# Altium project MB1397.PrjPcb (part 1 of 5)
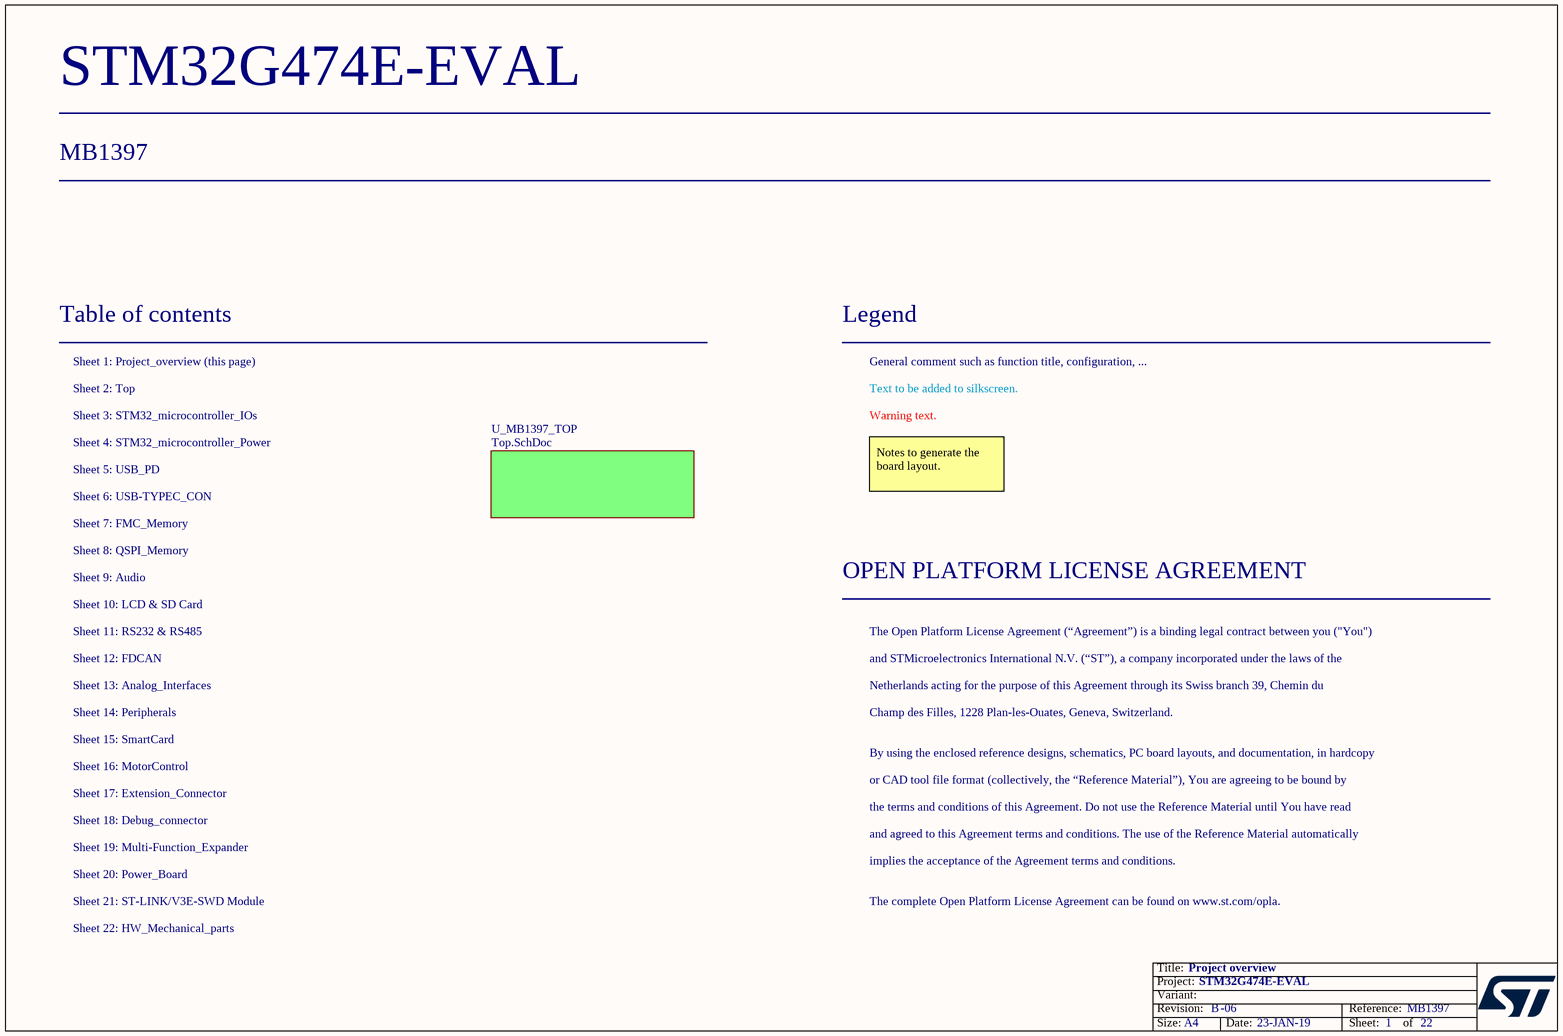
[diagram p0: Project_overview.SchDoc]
Board_Reference: MB1397; Board_PCB_Revision: B; Board_Name: STM32G474E-EVAL; Board_Document_Date: 23-JAN-19; Board_Assembly_Revision: 06
22 sheets, 834 parts. Net scope: flat (ports and power ports of the same name join across sheets).
Board file: MB1397.PcbDoc
Sheets:
  Project_overview.SchDoc
    U_MB1397_TOP = Top.SchDoc
      U_STM32_microcontroller_IOs = STM32_microcontroller_IOs.SchDoc
      U_FMC Memory = FMC_Memory.SchDoc
      U_Audio = Audio.SchDoc
      U_QSPI Memory = QSPI_Memory.SchDoc
      U_FDCAN = FDCAN.SchDoc
      U_LCD&SDcard = LCD&SDcard.SchDoc
      U_MotorControl = MotorControl.SchDoc
      U_SmartCard = SmartCard.SchDoc
      U_STM32_microcontroller_power = STM32_microcontroller_power.SchDoc
      U_Power_Board = Power_Board.SchDoc
      U_HW_Mechanical_Parts = HW_Mechanical_Parts.SchDoc
      U_Analog Interfaces = Analog_Interfaces.SchDoc
      U_Multi-Function Expander = Multi-Function_Expander.SchDoc
      U_Peripherals = Peripherals.SchDoc
      U_STLink_V3E_SWD = STLink_V3E_SWD.SchDoc
      U_ExtensionConnector = ExtensionConnector.SchDoc
      U_USB_PD = USB_PD.SchDoc
      U_Debug connector = Debug_connector.SchDoc
      U_RS232&RS485 = RS232&RS485.SchDoc
      U_USB-TYPEC_CON = USB-TYPEC_CON.SchDoc

## Sheet Project_overview.SchDoc: Project overview
size A4; IsUserConfigurable: Not used; Date: Not used; ApprovedBy: Not used; CheckedBy: Not used; Author: Not used; CompanyName: STMicroelectronics; DrawnBy: Not used; Engineer: Not used; Organization: Not used; Address1: Not used; Address2: Not used; Address3: Not used; Address4: Not used; DocumentNumber: Not used; Revision: Not used; SheetNumber: 1; SheetTotal: 22

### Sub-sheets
U_MB1397_TOP = Top.SchDoc: no entries

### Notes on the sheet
- Table of contents
- Sheet 1: Project_overview (this page)
- Legend
- General comment such as function title, configuration, ...
- Sheet 2: Top
- Sheet 4: STM32_microcontroller_Power
- Sheet 3: STM32_microcontroller_IOs
- Text to be added to silkscreen.
- Warning text.
- Sheet 6: USB-TYPEC_CON
- Sheet 5: USB_PD
- Notes to generate the board layout.
- Sheet 8: QSPI_Memory
- Sheet 7: FMC_Memory
- Sheet 9: Audio
- OPEN PLATFORM LICENSE AGREEMENT
- Sheet 10: LCD & SD Card
- Sheet 11: RS232 & RS485
- The Open Platform License Agreement (“Agreement”) is a binding legal contract between you ("You")
- Sheet 14: Peripherals
- Sheet 12: FDCAN
- Sheet 13: Analog_Interfaces
- and STMicroelectronics International N.V. (“ST”), a company incorporated under the laws of the
- Netherlands acting for the purpose of this Agreement through its Swiss branch 39, Chemin du
- Champ des Filles, 1228 Plan-les-Ouates, Geneva, Switzerland.
- Sheet 16: MotorControl
- Sheet 15: SmartCard
- By using the enclosed reference designs, schematics, PC board layouts, and documentation, in hardcopy
- or CAD tool file format (collectively, the “Reference Material”), You are agreeing to be bound by
- Sheet 18: Debug_connector
- Sheet 17: Extension_Connector
- Sheet 19: Multi-Function_Expander
- the terms and conditions of this Agreement. Do not use the Reference Material until You have read
- and agreed to this Agreement terms and conditions. The use of the Reference Material automatically
- Sheet 20: Power_Board
- Sheet 21: ST-LINK/V3E-SWD Module
- implies the acceptance of the Agreement terms and conditions.
- The complete Open Platform License Agreement can be found on www.st.com/opla.
- Sheet 22: HW_Mechanical_parts

## Sheet Top.SchDoc: MB1397 TOP
size A3; Date: Not used; ApprovedBy: Not used; CheckedBy: Not used; Author: Not used; CompanyName: STMicroelectronics; DrawnBy: Not used; Engineer: Not used; Organization: Not used; Address1: Not used; Address2: Not used; Address3: Not used; Address4: Not used; DocumentNumber: Not used; Revision: Not used; SheetNumber: 2; SheetTotal: 22
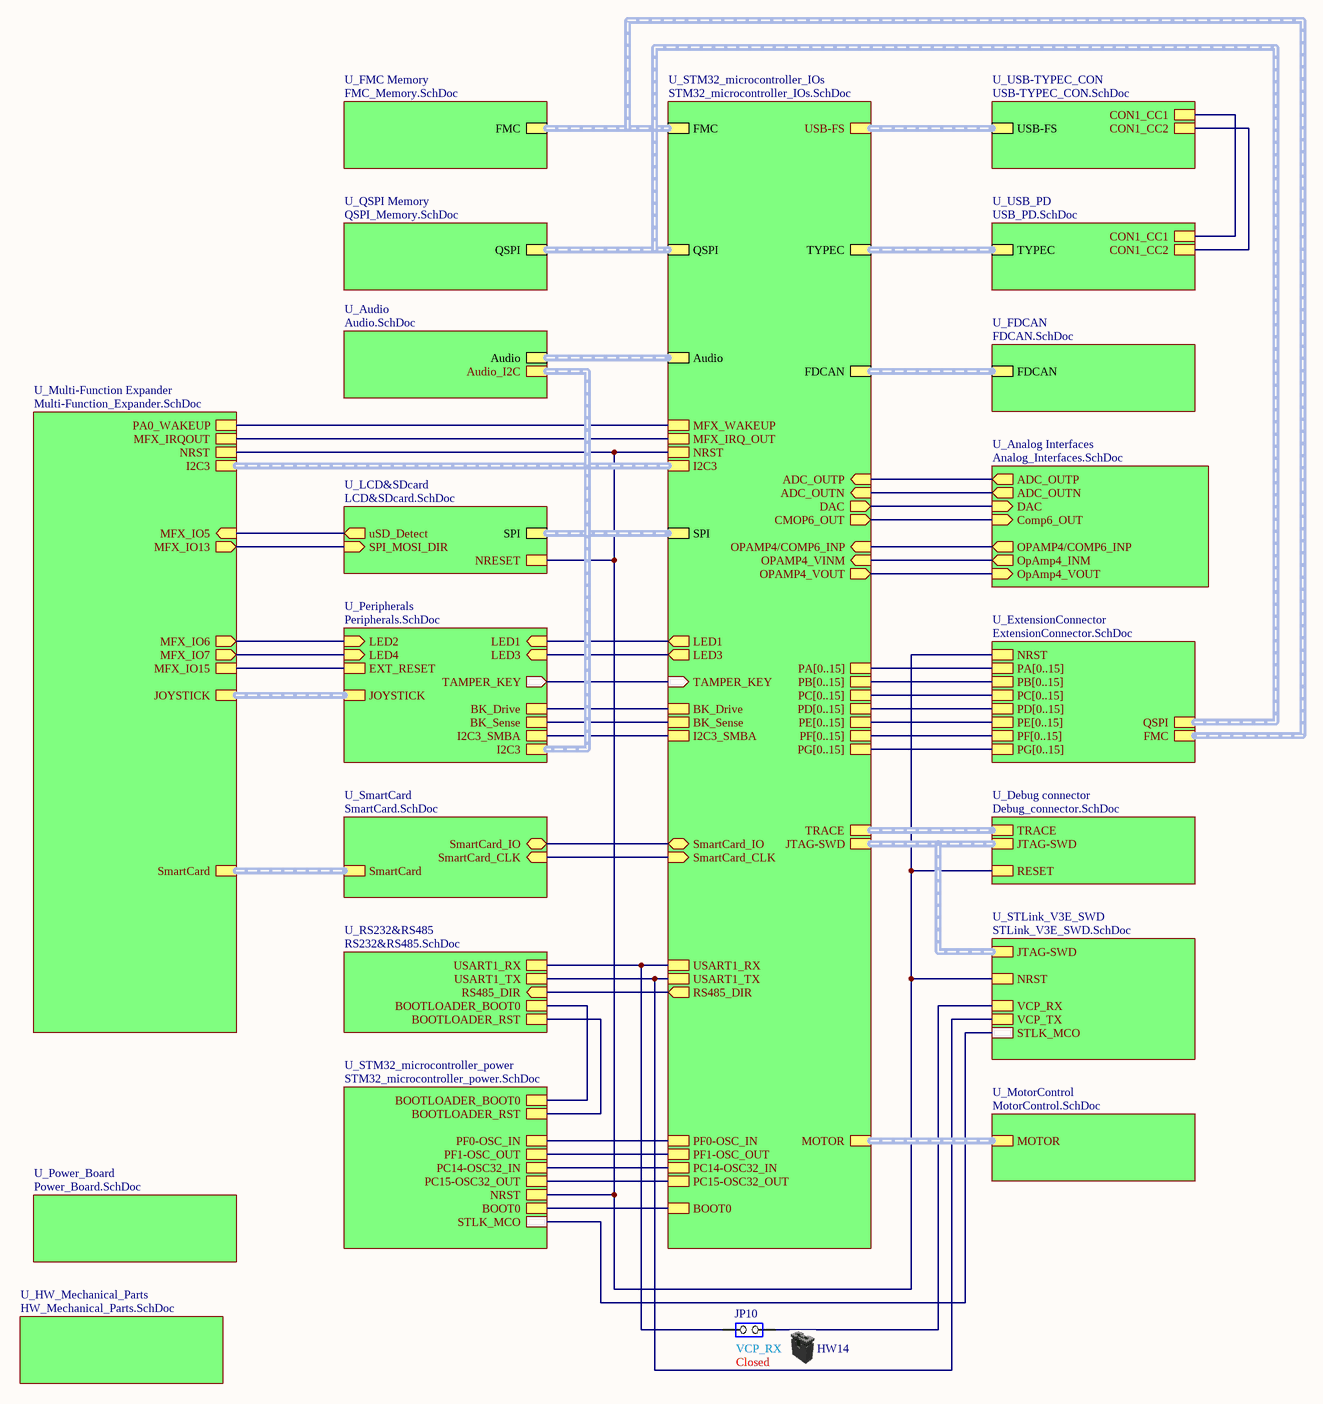
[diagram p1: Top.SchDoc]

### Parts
HW14  Shunt Black 2.54mm  (value not drawn)  (mechanical)
JP10  Jumper_Header 2x1  [CON_SAMTEC_TSW-102-07-G-S]  (value not drawn)

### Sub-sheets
U_Analog Interfaces = Analog_Interfaces.SchDoc: ADC_OUTP (out), ADC_OUTN (out), Comp6_OUT (in), OpAmp4_INM (out), OpAmp4_VOUT (in), DAC (in), OPAMP4/COMP6_INP (out)
U_Audio = Audio.SchDoc: Audio (harness SAI), Audio_I2C (harness I2C3)
U_Debug connector = Debug_connector.SchDoc: TRACE (harness TRACE), JTAG-SWD (harness JTAG-SWD), RESET
U_ExtensionConnector = ExtensionConnector.SchDoc: NRST, PA[0..15], PB[0..15], PC[0..15], PD[0..15], PE[0..15], PF[0..15], PG[0..15], QSPI (harness QSPI), FMC (harness FMC)
U_FDCAN = FDCAN.SchDoc: FDCAN (harness FDCAN)
U_FMC Memory = FMC_Memory.SchDoc: FMC (harness FMC)
U_HW_Mechanical_Parts = HW_Mechanical_Parts.SchDoc: no entries
U_LCD&SDcard = LCD&SDcard.SchDoc: SPI (harness SPI), SPI_MOSI_DIR (in), uSD_Detect (out), NRESET
U_MotorControl = MotorControl.SchDoc: MOTOR (harness MOTOR)
U_Multi-Function Expander = Multi-Function_Expander.SchDoc: MFX_IRQOUT, MFX_IO15, PA0_WAKEUP, JOYSTICK (harness JOYSTICK), SmartCard (harness SmartCard), I2C3 (harness I2C3), MFX_IO7 (out), MFX_IO6 (out), MFX_IO5 (in), MFX_IO13 (out), NRST
U_Peripherals = Peripherals.SchDoc: LED4 (in), LED3 (in), LED1 (in), LED2 (in), TAMPER_KEY (out), EXT_RESET, JOYSTICK (harness JOYSTICK), BK_Sense, BK_Drive, I2C3 (harness I2C3), I2C3_SMBA
U_Power_Board = Power_Board.SchDoc: no entries
U_QSPI Memory = QSPI_Memory.SchDoc: QSPI (harness QSPI)
U_RS232&RS485 = RS232&RS485.SchDoc: BOOTLOADER_BOOT0, BOOTLOADER_RST, USART1_RX, USART1_TX, RS485_DIR (in)
U_SmartCard = SmartCard.SchDoc: SmartCard_IO (bidir), SmartCard_CLK (in), SmartCard (harness SmartCard)
U_STLink_V3E_SWD = STLink_V3E_SWD.SchDoc: NRST, VCP_TX, VCP_RX, STLK_MCO, JTAG-SWD (harness JTAG-SWD)
U_STM32_microcontroller_IOs = STM32_microcontroller_IOs.SchDoc: FMC (harness FMC), TAMPER_KEY (in), LED3 (out), LED1 (out), MOTOR (harness MOTOR), SPI (harness SPI), QSPI (harness QSPI), Audio (harness SAI), FDCAN (harness FDCAN), TYPEC (harness USB-TYPEC), TRACE (harness TRACE), SmartCard_IO (bidir), PF1-OSC_OUT, PC14-OSC32_IN, PC15-OSC32_OUT, I2C3 (harness I2C3), SmartCard_CLK (in), PF0-OSC_IN, BK_Drive, NRST, USB-FS (harness USB-FS), JTAG-SWD (harness JTAG-SWD), BOOT0, BK_Sense, DAC (out), PC[0..15], PB[0..15], PE[0..15], PF[0..15], PG[0..15], PA[0..15], PD[0..15], CMOP6_OUT (out), ADC_OUTN (in), OPAMP4_VOUT (out), ADC_OUTP (in), OPAMP4_VINM (in), OPAMP4/COMP6_INP (in), I2C3_SMBA, MFX_WAKEUP, MFX_IRQ_OUT, USART1_RX, USART1_TX, RS485_DIR (out)
U_STM32_microcontroller_power = STM32_microcontroller_power.SchDoc: BOOTLOADER_BOOT0, BOOTLOADER_RST, NRST, BOOT0, PC14-OSC32_IN, PC15-OSC32_OUT, STLK_MCO, PF0-OSC_IN, PF1-OSC_OUT
U_USB-TYPEC_CON = USB-TYPEC_CON.SchDoc: USB-FS (harness USB-FS), CON1_CC1, CON1_CC2
U_USB_PD = USB_PD.SchDoc: TYPEC (harness USB-TYPEC), CON1_CC2, CON1_CC1

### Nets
NetJP10_1: JP10.1(COMMON) ; sheet U_STLink_V3E_SWD/VCP_RX
NetJP10_2: JP10.2(NO) ; sheet U_STM32_microcontroller_IOs/USART1_RX, sheet U_RS232&RS485/USART1_RX
(unnamed): sheet U_STM32_microcontroller_IOs/TAMPER_KEY, sheet U_Peripherals/TAMPER_KEY
(unnamed): sheet U_STM32_microcontroller_IOs/LED3, sheet U_Peripherals/LED3  [a separate net that carries the same name]
(unnamed): sheet U_STM32_microcontroller_IOs/LED1, sheet U_Peripherals/LED1  [a separate net that carries the same name]
(unnamed): sheet U_STM32_microcontroller_IOs/SmartCard_IO, sheet U_SmartCard/SmartCard_IO  [a separate net that carries the same name]
(unnamed): sheet U_STM32_microcontroller_IOs/PF1-OSC_OUT, sheet U_STM32_microcontroller_power/PF1-OSC_OUT  [a separate net that carries the same name]
(unnamed): sheet U_STM32_microcontroller_IOs/PC14-OSC32_IN, sheet U_STM32_microcontroller_power/PC14-OSC32_IN  [a separate net that carries the same name]
(unnamed): sheet U_STM32_microcontroller_IOs/PC15-OSC32_OUT, sheet U_STM32_microcontroller_power/PC15-OSC32_OUT  [a separate net that carries the same name]
(unnamed): sheet U_STM32_microcontroller_IOs/SmartCard_CLK, sheet U_SmartCard/SmartCard_CLK  [a separate net that carries the same name]
(unnamed): sheet U_STM32_microcontroller_IOs/PF0-OSC_IN, sheet U_STM32_microcontroller_power/PF0-OSC_IN  [a separate net that carries the same name]
(unnamed): sheet U_STM32_microcontroller_IOs/BK_Drive, sheet U_Peripherals/BK_Drive  [a separate net that carries the same name]
(unnamed): sheet U_STM32_microcontroller_IOs/NRST, sheet U_LCD&SDcard/NRESET, sheet U_STM32_microcontroller_power/NRST, sheet U_Multi-Function Expander/NRST, sheet U_STLink_V3E_SWD/NRST, sheet U_ExtensionConnector/NRST, sheet U_Debug connector/RESET  [a separate net that carries the same name]
(unnamed): sheet U_STM32_microcontroller_IOs/BOOT0, sheet U_STM32_microcontroller_power/BOOT0  [a separate net that carries the same name]
(unnamed): sheet U_STM32_microcontroller_IOs/BK_Sense, sheet U_Peripherals/BK_Sense  [a separate net that carries the same name]
(unnamed): sheet U_STM32_microcontroller_IOs/DAC, sheet U_Analog Interfaces/DAC  [a separate net that carries the same name]
(unnamed): sheet U_STM32_microcontroller_IOs/CMOP6_OUT, sheet U_Analog Interfaces/Comp6_OUT  [a separate net that carries the same name]
(unnamed): sheet U_STM32_microcontroller_IOs/ADC_OUTN, sheet U_Analog Interfaces/ADC_OUTN  [a separate net that carries the same name]
(unnamed): sheet U_STM32_microcontroller_IOs/OPAMP4_VOUT, sheet U_Analog Interfaces/OpAmp4_VOUT  [a separate net that carries the same name]
(unnamed): sheet U_STM32_microcontroller_IOs/ADC_OUTP, sheet U_Analog Interfaces/ADC_OUTP  [a separate net that carries the same name]
(unnamed): sheet U_STM32_microcontroller_IOs/OPAMP4_VINM, sheet U_Analog Interfaces/OpAmp4_INM  [a separate net that carries the same name]
(unnamed): sheet U_STM32_microcontroller_IOs/OPAMP4/COMP6_INP, sheet U_Analog Interfaces/OPAMP4/COMP6_INP  [a separate net that carries the same name]
(unnamed): sheet U_STM32_microcontroller_IOs/I2C3_SMBA, sheet U_Peripherals/I2C3_SMBA  [a separate net that carries the same name]
(unnamed): sheet U_STM32_microcontroller_IOs/MFX_WAKEUP, sheet U_Multi-Function Expander/PA0_WAKEUP  [a separate net that carries the same name]
(unnamed): sheet U_STM32_microcontroller_IOs/MFX_IRQ_OUT, sheet U_Multi-Function Expander/MFX_IRQOUT  [a separate net that carries the same name]
(unnamed): sheet U_STM32_microcontroller_IOs/USART1_TX, sheet U_STLink_V3E_SWD/VCP_TX, sheet U_RS232&RS485/USART1_TX  [a separate net that carries the same name]
(unnamed): sheet U_STM32_microcontroller_IOs/RS485_DIR, sheet U_RS232&RS485/RS485_DIR  [a separate net that carries the same name]
(unnamed): sheet U_LCD&SDcard/SPI_MOSI_DIR, sheet U_Multi-Function Expander/MFX_IO13  [a separate net that carries the same name]
(unnamed): sheet U_LCD&SDcard/uSD_Detect, sheet U_Multi-Function Expander/MFX_IO5  [a separate net that carries the same name]
(unnamed): sheet U_STM32_microcontroller_power/BOOTLOADER_BOOT0, sheet U_RS232&RS485/BOOTLOADER_BOOT0  [a separate net that carries the same name]
(unnamed): sheet U_STM32_microcontroller_power/BOOTLOADER_RST, sheet U_RS232&RS485/BOOTLOADER_RST  [a separate net that carries the same name]
(unnamed): sheet U_STM32_microcontroller_power/STLK_MCO, sheet U_STLink_V3E_SWD/STLK_MCO  [a separate net that carries the same name]
(unnamed): sheet U_Multi-Function Expander/MFX_IO15, sheet U_Peripherals/EXT_RESET  [a separate net that carries the same name]
(unnamed): sheet U_Multi-Function Expander/MFX_IO7, sheet U_Peripherals/LED4  [a separate net that carries the same name]
(unnamed): sheet U_Multi-Function Expander/MFX_IO6, sheet U_Peripherals/LED2  [a separate net that carries the same name]
(unnamed): sheet U_USB_PD/CON1_CC2, sheet U_USB-TYPEC_CON/CON1_CC2  [a separate net that carries the same name]
(unnamed): sheet U_USB_PD/CON1_CC1, sheet U_USB-TYPEC_CON/CON1_CC1  [a separate net that carries the same name]

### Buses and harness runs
bus sheet U_ExtensionConnector/PA[0..15] = sheet U_STM32_microcontroller_IOs/PA[0..15]
bus sheet U_ExtensionConnector/PB[0..15] = sheet U_STM32_microcontroller_IOs/PB[0..15]
bus sheet U_ExtensionConnector/PC[0..15] = sheet U_STM32_microcontroller_IOs/PC[0..15]
bus sheet U_ExtensionConnector/PD[0..15] = sheet U_STM32_microcontroller_IOs/PD[0..15]
bus sheet U_ExtensionConnector/PE[0..15] = sheet U_STM32_microcontroller_IOs/PE[0..15]
bus sheet U_ExtensionConnector/PF[0..15] = sheet U_STM32_microcontroller_IOs/PF[0..15]
bus sheet U_ExtensionConnector/PG[0..15] = sheet U_STM32_microcontroller_IOs/PG[0..15]
harness sheet U_Audio/Audio = sheet U_STM32_microcontroller_IOs/Audio
harness sheet U_Audio/Audio_I2C = sheet U_Multi-Function Expander/I2C3 = sheet U_Peripherals/I2C3 = sheet U_STM32_microcontroller_IOs/I2C3
harness sheet U_Debug connector/JTAG-SWD = sheet U_STLink_V3E_SWD/JTAG-SWD = sheet U_STM32_microcontroller_IOs/JTAG-SWD
harness sheet U_Debug connector/TRACE = sheet U_STM32_microcontroller_IOs/TRACE
harness sheet U_ExtensionConnector/FMC = sheet U_FMC Memory/FMC = sheet U_STM32_microcontroller_IOs/FMC
harness sheet U_ExtensionConnector/QSPI = sheet U_QSPI Memory/QSPI = sheet U_STM32_microcontroller_IOs/QSPI
harness sheet U_FDCAN/FDCAN = sheet U_STM32_microcontroller_IOs/FDCAN
harness sheet U_LCD&SDcard/SPI = sheet U_STM32_microcontroller_IOs/SPI
harness sheet U_MotorControl/MOTOR = sheet U_STM32_microcontroller_IOs/MOTOR
harness sheet U_Multi-Function Expander/JOYSTICK = sheet U_Peripherals/JOYSTICK
harness sheet U_Multi-Function Expander/SmartCard = sheet U_SmartCard/SmartCard
harness sheet U_STM32_microcontroller_IOs/TYPEC = sheet U_USB_PD/TYPEC
harness sheet U_STM32_microcontroller_IOs/USB-FS = sheet U_USB-TYPEC_CON/USB-FS

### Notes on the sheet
- Closed
- VCP_RX

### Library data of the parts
HW14 = MCD-00043: SHUNT 2.54mm BLACK; Part_Type: Mechanical; Manufacturer_Part_Number: SNT-100-BK-G; Manufacturer: SAMTEC; Provided_By: SUBCO; Initial_Board_Reference: MB1274; Value: SNT-100-BK-G; Path: ws/MCD_ApplicationBoards/Lists/MCDPARTSdatabase; Item Type: Item
JP10 = MCD-00045: Header, 2x1, 2,54mm, VR, TH, Height 5.84mm/2.54mm; Manufacturer_Part_Number: TSW-102-07-x-S; Manufacturer: SAMTEC; Part_Type: Connector; Value: Shunt not fitted; Provided_By: SUBCO; Initial_Board_Reference: MB1274; Path: ws/MCD_ApplicationBoards/Lists/MCDPARTSdatabase; Item Type: Item

## Sheet STM32_microcontroller_IOs.SchDoc: STM32_microcontroller_IOs
size A3; Date: Not used; ApprovedBy: Not used; CheckedBy: Not used; Author: Not used; CompanyName: STMicroelectronics; DrawnBy: Not used; Engineer: Not used; Organization: Not used; Address1: Not used; Address2: Not used; Address3: Not used; Address4: Not used; DocumentNumber: Not used; Revision: Not used; SheetNumber: 3; SheetTotal: 22
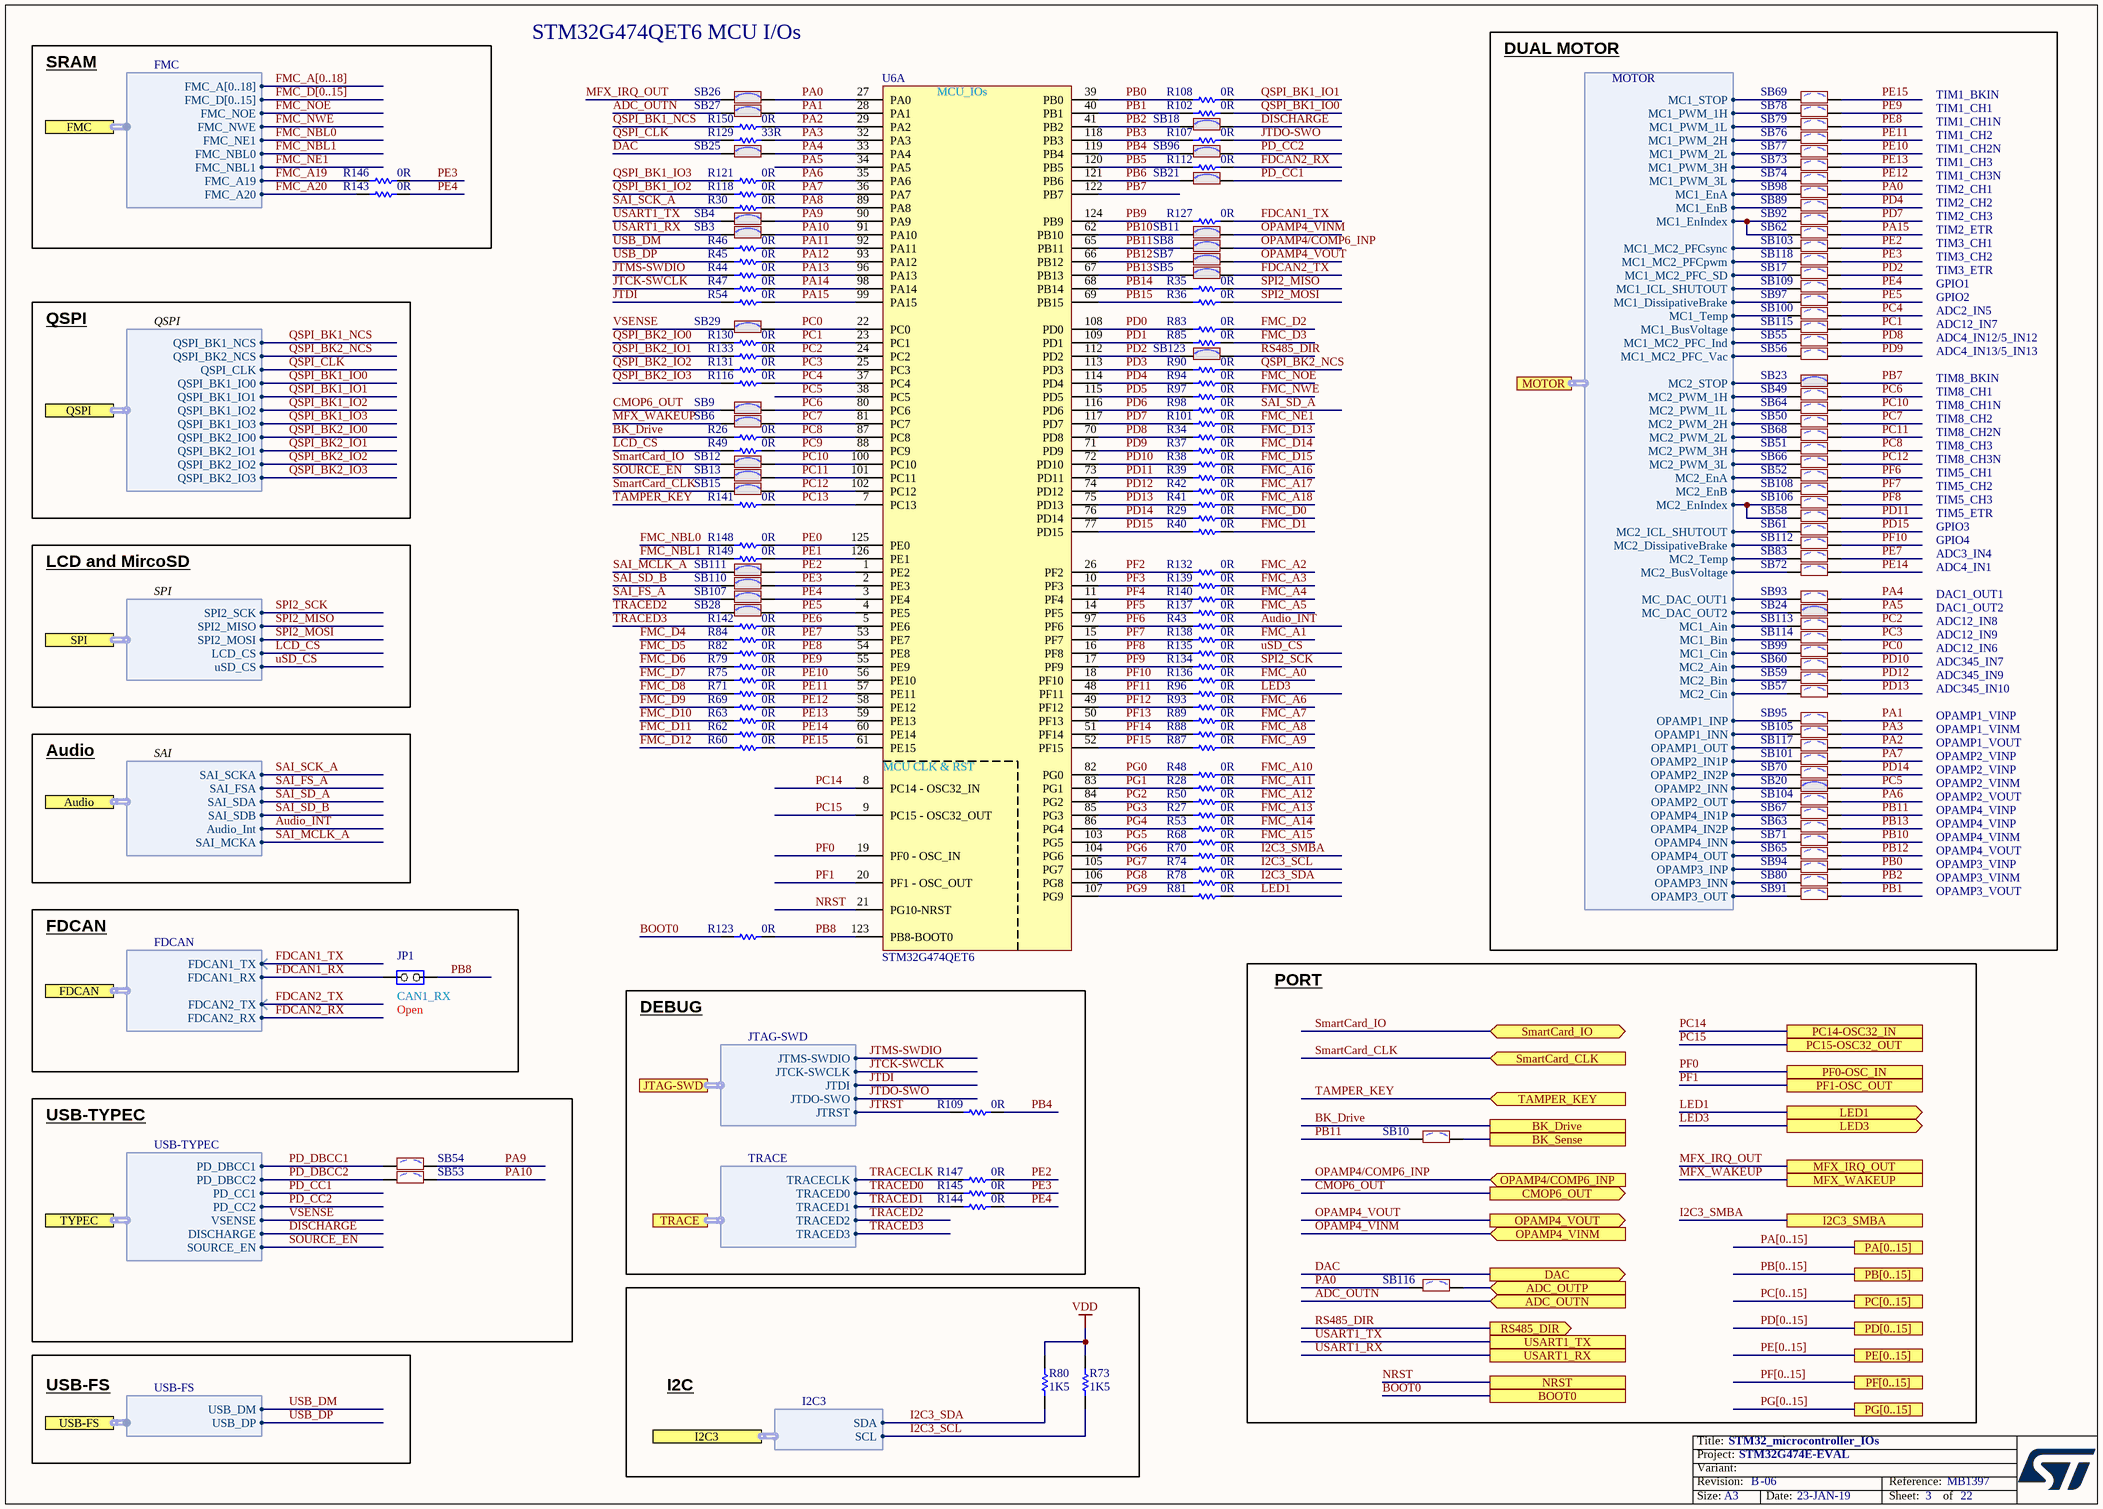
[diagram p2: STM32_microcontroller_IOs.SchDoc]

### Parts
JP1  Jumper_Header 2x1  [CON_SAMTEC_TSW-102-07-G-S]  (value not drawn)
R26  value 0R  [R0402]  (hidden comment: Resistor)
R27  value 0R  [R0402]  (hidden comment: Resistor)
R28  value 0R  [R0402]  (hidden comment: Resistor)
R29  value 0R  [R0402]  (hidden comment: Resistor)
R30  value 0R  [R0402]  (hidden comment: Resistor)
R34  value 0R  [R0402]  (hidden comment: Resistor)
R35  value 0R  [R0402]  (hidden comment: Resistor)
R36  value 0R  [R0402]  (hidden comment: Resistor)
R37  value 0R  [R0402]  (hidden comment: Resistor)
R38  value 0R  [R0402]  (hidden comment: Resistor)
R39  value 0R  [R0402]  (hidden comment: Resistor)
R40  value 0R  [R0402]  (hidden comment: Resistor)
R41  value 0R  [R0402]  (hidden comment: Resistor)
R42  value 0R  [R0402]  (hidden comment: Resistor)
R43  value 0R  [R0402]  (hidden comment: Resistor)
R44  value 0R  [R0402]  (hidden comment: Resistor)
R45  value 0R  [R0402]  (hidden comment: Resistor)
R46  value 0R  [R0402]  (hidden comment: Resistor)
R47  value 0R  [R0402]  (hidden comment: Resistor)
R48  value 0R  [R0402]  (hidden comment: Resistor)
R49  value 0R  [R0402]  (hidden comment: Resistor)
R50  value 0R  [R0402]  (hidden comment: Resistor)
R53  value 0R  [R0402]  (hidden comment: Resistor)
R54  value 0R  [R0402]  (hidden comment: Resistor)
R60  value 0R  [R0402]  (hidden comment: Resistor)
R62  value 0R  [R0402]  (hidden comment: Resistor)
R63  value 0R  [R0402]  (hidden comment: Resistor)
R68  value 0R  [R0402]  (hidden comment: Resistor)
R69  value 0R  [R0402]  (hidden comment: Resistor)
R70  value 0R  [R0402]  (hidden comment: Resistor)
R71  value 0R  [R0402]  (hidden comment: Resistor)
R73  value 1K5  [R0603]  (hidden comment: Resistor)
R74  value 0R  [R0402]  (hidden comment: Resistor)
R75  value 0R  [R0402]  (hidden comment: Resistor)
R78  value 0R  [R0402]  (hidden comment: Resistor)
R79  value 0R  [R0402]  (hidden comment: Resistor)
R80  value 1K5  [R0603]  (hidden comment: Resistor)
R81  value 0R  [R0402]  (hidden comment: Resistor)
R82  value 0R  [R0402]  (hidden comment: Resistor)
R83  value 0R  [R0402]  (hidden comment: Resistor)
R84  value 0R  [R0402]  (hidden comment: Resistor)
R85  value 0R  [R0402]  (hidden comment: Resistor)
R87  value 0R  [R0402]  (hidden comment: Resistor)
R88  value 0R  [R0402]  (hidden comment: Resistor)
R89  value 0R  [R0402]  (hidden comment: Resistor)
R90  value 0R  [R0402]  (hidden comment: Resistor)
R93  value 0R  [R0402]  (hidden comment: Resistor)
R94  value 0R  [R0402]  (hidden comment: Resistor)
R96  value 0R  [R0402]  (hidden comment: Resistor)
R97  value 0R  [R0402]  (hidden comment: Resistor)
R98  value 0R  [R0402]  (hidden comment: Resistor)
R101  value 0R  [R0402]  (hidden comment: Resistor)
R102  value 0R  [R0402]  (hidden comment: Resistor)
R107  value 0R  [R0402]  (hidden comment: Resistor)
R108  value 0R  [R0402]  (hidden comment: Resistor)
R109  value 0R  [R0402]  (hidden comment: Resistor)
R112  value 0R  [R0402]  (hidden comment: Resistor)
R116  value 0R  [R0402]  (hidden comment: Resistor)
R118  value 0R  [R0402]  (hidden comment: Resistor)
R121  value 0R  [R0402]  (hidden comment: Resistor)
R123  value 0R  [R0402]  (hidden comment: Resistor)
R127  value 0R  [R0402]  (hidden comment: Resistor)
R129  value 33R  [R0402]  (hidden comment: Resistor)
R130  value 0R  [R0402]  (hidden comment: Resistor)
R131  value 0R  [R0402]  (hidden comment: Resistor)
R132  value 0R  [R0402]  (hidden comment: Resistor)
R133  value 0R  [R0402]  (hidden comment: Resistor)
R134  value 0R  [R0402]  (hidden comment: Resistor)
R135  value 0R  [R0402]  (hidden comment: Resistor)
R136  value 0R  [R0402]  (hidden comment: Resistor)
R137  value 0R  [R0402]  (hidden comment: Resistor)
R138  value 0R  [R0402]  (hidden comment: Resistor)
R139  value 0R  [R0402]  (hidden comment: Resistor)
R140  value 0R  [R0402]  (hidden comment: Resistor)
R141  value 0R  [R0402]  (hidden comment: Resistor)
R142  value 0R  [R0402]  (hidden comment: Resistor)
R143  value 0R  [R0402]  (hidden comment: Resistor)
R144  value 0R  [R0402]  (hidden comment: Resistor)
R145  value 0R  [R0402]  (hidden comment: Resistor)
R146  value 0R  [R0402]  (hidden comment: Resistor)
R147  value 0R  [R0402]  (hidden comment: Resistor)
R148  value 0R  [R0402]  (hidden comment: Resistor)
R149  value 0R  [R0402]  (hidden comment: Resistor)
R150  value 0R  [R0402]  (hidden comment: Resistor)
SB3  SB_ON  [SOLDER-BRIDGE_R0603-0R]  (value not drawn)
SB4  SB_ON  [SOLDER-BRIDGE_R0603-0R]  (value not drawn)
SB5  SB_ON  [SOLDER-BRIDGE_R0603-0R]  (value not drawn)
SB6  SB_ON  [SOLDER-BRIDGE_R0603-0R]  (value not drawn)
SB7  SB_ON  [SOLDER-BRIDGE_R0603-0R]  (value not drawn)
SB8  SB_ON  [SOLDER-BRIDGE_R0603-0R]  (value not drawn)
SB9  SB_ON  [SOLDER-BRIDGE_R0603-0R]  (value not drawn)
SB10  SB_OFF  [SOLDER-BRIDGE_R0603-0R]  (value not drawn)
SB11  SB_ON  [SOLDER-BRIDGE_R0603-0R]  (value not drawn)
SB12  SB_ON  [SOLDER-BRIDGE_R0603-0R]  (value not drawn)
SB13  SB_ON  [SOLDER-BRIDGE_R0603-0R]  (value not drawn)
SB15  SB_ON  [SOLDER-BRIDGE_R0603-0R]  (value not drawn)
SB17  SB_OFF  [SOLDER-BRIDGE_R0603-0R]  (value not drawn)
SB18  SB_ON  [SOLDER-BRIDGE_R0603-0R]  (value not drawn)
SB20  SB_ON  [SOLDER-BRIDGE_R0603-0R]  (value not drawn)
SB21  SB_ON  [SOLDER-BRIDGE_R0603-0R]  (value not drawn)
SB23  SB_ON  [SOLDER-BRIDGE_R0603-0R]  (value not drawn)
SB24  SB_ON  [SOLDER-BRIDGE_R0603-0R]  (value not drawn)
SB25  SB_ON  [SOLDER-BRIDGE_R0603-0R]  (value not drawn)
SB26  SB_ON  [SOLDER-BRIDGE_R0603-0R]  (value not drawn)
SB27  SB_ON  [SOLDER-BRIDGE_R0603-0R]  (value not drawn)
SB28  SB_ON  [SOLDER-BRIDGE_R0603-0R]  (value not drawn)
SB29  SB_ON  [SOLDER-BRIDGE_R0603-0R]  (value not drawn)
SB49  SB_OFF  [SOLDER-BRIDGE_R0603-0R]  (value not drawn)
SB50  SB_OFF  [SOLDER-BRIDGE_R0603-0R]  (value not drawn)
SB51  SB_OFF  [SOLDER-BRIDGE_R0603-0R]  (value not drawn)
SB52  SB_OFF  [SOLDER-BRIDGE_R0603-0R]  (value not drawn)
SB53  SB_OFF  [SOLDER-BRIDGE_R0603-0R]  (value not drawn)
SB54  SB_OFF  [SOLDER-BRIDGE_R0603-0R]  (value not drawn)
SB55  SB_OFF  [SOLDER-BRIDGE_R0603-0R]  (value not drawn)
SB56  SB_OFF  [SOLDER-BRIDGE_R0603-0R]  (value not drawn)
SB57  SB_OFF  [SOLDER-BRIDGE_R0603-0R]  (value not drawn)
SB58  SB_OFF  [SOLDER-BRIDGE_R0603-0R]  (value not drawn)
SB59  SB_OFF  [SOLDER-BRIDGE_R0603-0R]  (value not drawn)
SB60  SB_OFF  [SOLDER-BRIDGE_R0603-0R]  (value not drawn)
SB61  SB_OFF  [SOLDER-BRIDGE_R0603-0R]  (value not drawn)
SB62  SB_OFF  [SOLDER-BRIDGE_R0603-0R]  (value not drawn)
SB63  SB_OFF  [SOLDER-BRIDGE_R0603-0R]  (value not drawn)
SB64  SB_OFF  [SOLDER-BRIDGE_R0603-0R]  (value not drawn)
SB65  SB_OFF  [SOLDER-BRIDGE_R0603-0R]  (value not drawn)
SB66  SB_OFF  [SOLDER-BRIDGE_R0603-0R]  (value not drawn)
SB67  SB_OFF  [SOLDER-BRIDGE_R0603-0R]  (value not drawn)
SB68  SB_OFF  [SOLDER-BRIDGE_R0603-0R]  (value not drawn)
SB69  SB_OFF  [SOLDER-BRIDGE_R0603-0R]  (value not drawn)
SB70  SB_OFF  [SOLDER-BRIDGE_R0603-0R]  (value not drawn)
SB71  SB_OFF  [SOLDER-BRIDGE_R0603-0R]  (value not drawn)
SB72  SB_OFF  [SOLDER-BRIDGE_R0603-0R]  (value not drawn)
SB73  SB_OFF  [SOLDER-BRIDGE_R0603-0R]  (value not drawn)
SB74  SB_OFF  [SOLDER-BRIDGE_R0603-0R]  (value not drawn)
SB76  SB_OFF  [SOLDER-BRIDGE_R0603-0R]  (value not drawn)
SB77  SB_OFF  [SOLDER-BRIDGE_R0603-0R]  (value not drawn)
SB78  SB_OFF  [SOLDER-BRIDGE_R0603-0R]  (value not drawn)
SB79  SB_OFF  [SOLDER-BRIDGE_R0603-0R]  (value not drawn)
SB80  SB_OFF  [SOLDER-BRIDGE_R0603-0R]  (value not drawn)
SB83  SB_OFF  [SOLDER-BRIDGE_R0603-0R]  (value not drawn)
SB89  SB_OFF  [SOLDER-BRIDGE_R0603-0R]  (value not drawn)
SB91  SB_OFF  [SOLDER-BRIDGE_R0603-0R]  (value not drawn)
SB92  SB_OFF  [SOLDER-BRIDGE_R0603-0R]  (value not drawn)
SB93  SB_OFF  [SOLDER-BRIDGE_R0603-0R]  (value not drawn)
SB94  SB_OFF  [SOLDER-BRIDGE_R0603-0R]  (value not drawn)
SB95  SB_OFF  [SOLDER-BRIDGE_R0603-0R]  (value not drawn)
SB96  SB_ON  [SOLDER-BRIDGE_R0603-0R]  (value not drawn)
SB97  SB_OFF  [SOLDER-BRIDGE_R0603-0R]  (value not drawn)
SB98  SB_OFF  [SOLDER-BRIDGE_R0603-0R]  (value not drawn)
SB99  SB_OFF  [SOLDER-BRIDGE_R0603-0R]  (value not drawn)
SB100  SB_OFF  [SOLDER-BRIDGE_R0603-0R]  (value not drawn)
SB101  SB_OFF  [SOLDER-BRIDGE_R0603-0R]  (value not drawn)
SB103  SB_OFF  [SOLDER-BRIDGE_R0603-0R]  (value not drawn)
SB104  SB_OFF  [SOLDER-BRIDGE_R0603-0R]  (value not drawn)
SB105  SB_OFF  [SOLDER-BRIDGE_R0603-0R]  (value not drawn)
SB106  SB_OFF  [SOLDER-BRIDGE_R0603-0R]  (value not drawn)
SB107  SB_ON  [SOLDER-BRIDGE_R0603-0R]  (value not drawn)
SB108  SB_OFF  [SOLDER-BRIDGE_R0603-0R]  (value not drawn)
SB109  SB_OFF  [SOLDER-BRIDGE_R0603-0R]  (value not drawn)
SB110  SB_ON  [SOLDER-BRIDGE_R0603-0R]  (value not drawn)
SB111  SB_ON  [SOLDER-BRIDGE_R0603-0R]  (value not drawn)
SB112  SB_OFF  [SOLDER-BRIDGE_R0603-0R]  (value not drawn)
SB113  SB_OFF  [SOLDER-BRIDGE_R0603-0R]  (value not drawn)
SB114  SB_OFF  [SOLDER-BRIDGE_R0603-0R]  (value not drawn)
SB115  SB_OFF  [SOLDER-BRIDGE_R0603-0R]  (value not drawn)
SB116  SB_OFF  [SOLDER-BRIDGE_R0603-0R]  (value not drawn)
SB117  SB_OFF  [SOLDER-BRIDGE_R0603-0R]  (value not drawn)
SB118  SB_OFF  [SOLDER-BRIDGE_R0603-0R]  (value not drawn)
SB123  SB_ON  [SOLDER-BRIDGE_R0603-0R]  (value not drawn)
U6  STM32G474QET6  [ICC_LQFP128_14X14_P040]  (part A of 2)

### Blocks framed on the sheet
SRAM: R143 R146
DUAL MOTOR: SB17 SB20 SB23 SB24 SB49-SB52 SB55-SB74 SB76-SB80 SB83 SB89 SB91-SB95 SB97-SB101 SB103-SB106 SB108 SB109 SB112-SB115 SB117 SB118
FDCAN: JP1
DEBUG: R109 R144 R145 R147
PORT: SB10 SB116
USB-TYPEC: SB53 SB54
I2C: R73 R80

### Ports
ADC_OUTN (in), ADC_OUTP (in), Audio (harness SAI), BK_Drive, BK_Sense, BOOT0, CMOP6_OUT (out), DAC (out), FDCAN (harness FDCAN), FMC (harness FMC), I2C3 (harness I2C3), I2C3_SMBA, JTAG-SWD (harness JTAG-SWD), LED1 (out), LED3 (out), MFX_IRQ_OUT, MFX_WAKEUP, MOTOR (harness MOTOR), NRST, OPAMP4/COMP6_INP (in), OPAMP4_VINM (in), OPAMP4_VOUT (out), PA[0..15], PB[0..15], PC14-OSC32_IN, PC15-OSC32_OUT, PC[0..15], PD[0..15], PE[0..15], PF0-OSC_IN, PF1-OSC_OUT, PF[0..15], PG[0..15], QSPI (harness QSPI), RS485_DIR (out), SmartCard_CLK (in), SmartCard_IO (bidir), SPI (harness SPI), TAMPER_KEY (in), TRACE (harness TRACE), TYPEC (harness USB-TYPEC), USART1_RX, USART1_TX, USB-FS (harness USB-FS)

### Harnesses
FMC: FMC_NWE, FMC_NOE, FMC_NE1, FMC_A[0..18], FMC_D[0..15], FMC_NBL0, FMC_NBL1, FMC_A19, FMC_A20
MOTOR: MC1_PWM_1H, MC1_PWM_1L, MC1_PWM_2H, MC1_PWM_2L, MC1_PWM_3H, MC1_PWM_3L, MC1_STOP, MC1_EnA, MC1_EnB, MC1_EnIndex, MC1_MC2_PFCsync, MC1_MC2_PFCpwm, MC1_MC2_PFC_SD, MC1_ICL_SHUTOUT, MC1_DissipativeBrake, MC1_Temp, MC1_BusVoltage, MC1_MC2_PFC_Ind, MC1_MC2_PFC_Vac, MC2_STOP, MC2_PWM_1H, MC2_PWM_1L, MC2_PWM_2H, MC2_PWM_2L, MC2_PWM_3H, MC2_PWM_3L, MC2_EnA, MC2_EnB, MC2_EnIndex, MC2_ICL_SHUTOUT, MC2_DissipativeBrake, MC2_Temp, MC2_BusVoltage, MC_DAC_OUT1, MC_DAC_OUT2, MC1_Ain, MC1_Bin, MC1_Cin, MC2_Ain, MC2_Bin, MC2_Cin, OPAMP1_INP, OPAMP1_INN, OPAMP1_OUT, OPAMP2_IN1P, OPAMP2_IN2P, OPAMP2_INN, OPAMP2_OUT, OPAMP4_IN1P, OPAMP4_IN2P, OPAMP4_INN, OPAMP4_OUT, OPAMP3_INP, OPAMP3_INN, OPAMP3_OUT
SPI: SPI2_SCK, SPI2_MISO, SPI2_MOSI, LCD_CS, uSD_CS
QSPI: QSPI_BK1_IO1, QSPI_BK1_IO0, QSPI_CLK, QSPI_BK1_NCS, QSPI_BK1_IO2, QSPI_BK1_IO3, QSPI_BK2_IO1, QSPI_BK2_IO0, QSPI_BK2_IO2, QSPI_BK2_IO3, QSPI_BK2_NCS
SAI: SAI_SDB, SAI_FSA, Audio_Int, SAI_SDA, SAI_SCKA, SAI_MCKA
FDCAN: FDCAN1_TX, FDCAN1_RX, FDCAN2_TX, FDCAN2_RX
USB-FS: USB_DM, USB_DP
JTAG-SWD: JTMS-SWDIO, JTCK-SWCLK, JTDI, JTDO-SWO, JTRST
TRACE: TRACECLK, TRACED0, TRACED1, TRACED2, TRACED3
I2C3: SDA, SCL
USB-TYPEC: PD_DBCC1, PD_DBCC2, PD_CC1, PD_CC2, VSENSE, DISCHARGE, SOURCE_EN

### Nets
VDD: R73.2 R80.2
ADC_OUTN: SB27.1 ; port ADC_OUTN
Audio_INT: R43.2 ; port Audio.Audio_Int
BK_Drive: R26.1 ; port BK_Drive
BOOT0: R123.1 ; port BOOT0
CMOP6_OUT: SB9.1 ; port CMOP6_OUT
DAC: SB25.1 ; port DAC
DISCHARGE: SB18.2 ; port TYPEC.DISCHARGE
FDCAN1_RX: JP1.2(NO) ; port FDCAN.FDCAN1_RX
FDCAN1_TX: R127.2 ; port FDCAN.FDCAN1_TX
FDCAN2_RX: R112.2 ; port FDCAN.FDCAN2_RX
FDCAN2_TX: SB5.2 ; port FDCAN.FDCAN2_TX
FMC_A0: R136.2  [project net A0]
FMC_A1: R138.2  [project net A1]
FMC_A2: R132.2  [project net A2]
FMC_A3: R139.2  [project net A3]
FMC_A4: R140.2  [project net A4]
FMC_A5: R137.2  [project net A5]
FMC_A6: R93.2  [project net A6]
FMC_A7: R89.2  [project net A7]
FMC_A8: R88.2  [project net A8]
FMC_A9: R87.2  [project net A9]
FMC_A10: R48.2  [project net A10]
FMC_A11: R28.2  [project net A11]
FMC_A12: R50.2  [project net A12]
FMC_A13: R27.2  [project net A13]
FMC_A14: R53.2  [project net A14]
FMC_A15: R68.2  [project net A15]
FMC_A16: R39.2  [project net A16]
FMC_A17: R42.2  [project net A17]
FMC_A18: R41.2  [project net A18]
FMC_A19: R146.1 ; port FMC.FMC_A19  [project net A19]
FMC_A20: R143.1 ; port FMC.FMC_A20  [project net A20]
FMC_D0: R29.2  [project net D0]
FMC_D1: R40.2  [project net D1]
FMC_D2: R83.2  [project net D2]
FMC_D3: R85.2  [project net D3]
FMC_D4: R84.1  [project net D4]
FMC_D5: R82.1  [project net D5]
FMC_D6: R79.1  [project net D6]
FMC_D7: R75.1  [project net D7]
FMC_D8: R71.1  [project net D8]
FMC_D9: R69.1  [project net D9]
FMC_D10: R63.1  [project net D10]
FMC_D11: R62.1  [project net D11]
FMC_D12: R60.1  [project net D12]
FMC_D13: R34.2  [project net D13]
FMC_D14: R37.2  [project net D14]
FMC_D15: R38.2  [project net D15]
FMC_NBL0: R148.1 ; port FMC.FMC_NE1
FMC_NBL1: R149.1 ; port FMC.FMC_NBL0
FMC_NE1: R101.2 ; port FMC.FMC_NBL1
FMC_NOE: R94.2 ; port FMC.FMC_NOE
FMC_NWE: R97.2 ; port FMC.FMC_NWE
I2C3_SCL: R73.1 R74.2 ; port I2C3.SCL
I2C3_SDA: R78.2 R80.1 ; port I2C3.SDA
I2C3_SMBA: R70.2 ; port I2C3_SMBA
JTCK-SWCLK: R47.1 ; port JTAG-SWD.JTCK-SWCLK
JTDI: R54.1 ; port JTAG-SWD.JTDI
JTDO-SWO: R107.2 ; port JTAG-SWD.JTDO-SWO
JTMS-SWDIO: R44.1 ; port JTAG-SWD.JTMS-SWDIO
JTRST: R109.1 ; port JTAG-SWD.JTRST
LCD_CS: R49.1 ; port SPI.LCD_CS
LED1: R81.2 ; port LED1
LED3: R96.2 ; port LED3
MC1_Ain: SB113.1 ; port MOTOR.MC1_Ain
MC1_Bin: SB114.1 ; port MOTOR.MC1_Bin
MC1_BusVoltage: SB115.1 ; port MOTOR.MC1_BusVoltage
MC1_Cin: SB99.1 ; port MOTOR.MC1_Cin
MC1_DissipativeBrake: SB97.1 ; port MOTOR.MC1_DissipativeBrake
MC1_EnA: SB98.1 ; port MOTOR.MC1_EnA
MC1_EnB: SB89.1 ; port MOTOR.MC1_EnB
MC1_EnIndex: SB62.1 SB92.1 ; port MOTOR.MC1_EnIndex
MC1_ICL_SHUTOUT: SB109.1 ; port MOTOR.MC1_ICL_SHUTOUT
MC1_MC2_PFC_Ind: SB55.1 ; port MOTOR.MC1_MC2_PFC_Ind
MC1_MC2_PFC_SD: SB17.1 ; port MOTOR.MC1_MC2_PFC_SD
MC1_MC2_PFC_Vac: SB56.1 ; port MOTOR.MC1_MC2_PFC_Vac
MC1_MC2_PFCpwm: SB118.1 ; port MOTOR.MC1_MC2_PFCpwm
MC1_MC2_PFCsync: SB103.1 ; port MOTOR.MC1_MC2_PFCsync
MC1_PWM_1H: SB78.1 ; port MOTOR.MC1_PWM_1H
MC1_PWM_1L: SB79.1 ; port MOTOR.MC1_PWM_1L
MC1_PWM_2H: SB76.1 ; port MOTOR.MC1_PWM_2H
MC1_PWM_2L: SB77.1 ; port MOTOR.MC1_PWM_2L
MC1_PWM_3H: SB73.1 ; port MOTOR.MC1_PWM_3H
MC1_PWM_3L: SB74.1 ; port MOTOR.MC1_PWM_3L
MC1_STOP: SB69.1 ; port MOTOR.MC1_STOP
MC1_Temp: SB100.1 ; port MOTOR.MC1_Temp
MC2_Ain: SB60.1 ; port MOTOR.MC2_Ain
MC2_Bin: SB59.1 ; port MOTOR.MC2_Bin
MC2_BusVoltage: SB72.1 ; port MOTOR.MC2_BusVoltage
MC2_Cin: SB57.1 ; port MOTOR.MC2_Cin
MC2_DissipativeBrake: SB112.1 ; port MOTOR.MC2_DissipativeBrake
MC2_EnA: SB52.1 ; port MOTOR.MC2_EnA
MC2_EnB: SB108.1 ; port MOTOR.MC2_EnB
MC2_EnIndex: SB58.1 SB106.1 ; port MOTOR.MC2_EnIndex
MC2_ICL_SHUTOUT: SB61.1 ; port MOTOR.MC2_ICL_SHUTOUT
MC2_PWM_1H: SB49.1 ; port MOTOR.MC2_PWM_1H
MC2_PWM_1L: SB64.1 ; port MOTOR.MC2_PWM_1L
MC2_PWM_2H: SB50.1 ; port MOTOR.MC2_PWM_2H
MC2_PWM_2L: SB68.1 ; port MOTOR.MC2_PWM_2L
MC2_PWM_3H: SB51.1 ; port MOTOR.MC2_PWM_3H
MC2_PWM_3L: SB66.1 ; port MOTOR.MC2_PWM_3L
MC2_STOP: SB23.1 ; port MOTOR.MC2_STOP
MC2_Temp: SB83.1 ; port MOTOR.MC2_Temp
MC_DAC_OUT1: SB93.1 ; port MOTOR.MC_DAC_OUT1
MC_DAC_OUT2: SB24.1 ; port MOTOR.MC_DAC_OUT2
MFX_IRQ_OUT: SB26.1 ; port MFX_IRQ_OUT
MFX_WAKEUP: SB6.1 ; port MFX_WAKEUP
NRST: U6.21(PG10-NRST) ; port NRST
OPAMP1_INN: SB105.1 ; port MOTOR.OPAMP1_INN
OPAMP1_INP: SB95.1 ; port MOTOR.OPAMP1_INP
OPAMP1_OUT: SB117.1 ; port MOTOR.OPAMP1_OUT
OPAMP2_IN1P: SB101.1 ; port MOTOR.OPAMP2_IN1P
OPAMP2_IN2P: SB70.1 ; port MOTOR.OPAMP2_IN2P
OPAMP2_INN: SB20.1 ; port MOTOR.OPAMP2_INN
OPAMP2_OUT: SB104.1 ; port MOTOR.OPAMP2_OUT
OPAMP3_INN: SB80.1 ; port MOTOR.OPAMP3_INN
OPAMP3_INP: SB94.1 ; port MOTOR.OPAMP3_INP
OPAMP3_OUT: SB91.1 ; port MOTOR.OPAMP3_OUT
OPAMP4/COMP6_INP: SB8.2 ; port OPAMP4/COMP6_INP
OPAMP4_IN1P: SB67.1 ; port MOTOR.OPAMP4_IN1P
OPAMP4_IN2P: SB63.1 ; port MOTOR.OPAMP4_IN2P
OPAMP4_INN: SB71.1 ; port MOTOR.OPAMP4_INN
OPAMP4_OUT: SB65.1 ; port MOTOR.OPAMP4_OUT
OPAMP4_VINM: SB11.2 ; port OPAMP4_VINM
OPAMP4_VOUT: SB7.2 ; port OPAMP4_VOUT
PA0: SB26.2 SB98.2 SB116.1 U6.27(PA0)
PA1: SB27.2 SB95.2 U6.28(PA1)
PA2: R150.2 SB117.2 U6.29(PA2)
PA3: R129.2 SB105.2 U6.32(PA3)
PA4: SB25.2 SB93.2 U6.33(PA4)
PA5: SB24.2 U6.34(PA5)
PA6: R121.2 SB104.2 U6.35(PA6)
PA7: R118.2 SB101.2 U6.36(PA7)
PA8: R30.2 U6.89(PA8)
PA9: SB4.2 SB54.2 U6.90(PA9)
PA10: SB3.2 SB53.2 U6.91(PA10)
PA11: R46.2 U6.92(PA11)
PA12: R45.2 U6.93(PA12)
PA13: R44.2 U6.96(PA13)
PA14: R47.2 U6.98(PA14)
PA15: R54.2 SB62.2 U6.99(PA15)
PB0: R108.1 SB94.2 U6.39(PB0)
PB1: R102.1 SB91.2 U6.40(PB1)
PB2: SB18.1 SB80.2 U6.41(PB2)
PB3: R107.1 U6.118(PB3)
PB4: R109.2 SB96.1 U6.119(PB4)
PB5: R112.1 U6.120(PB5)
PB6: SB21.1 U6.121(PB6)
PB7: SB23.2 U6.122(PB7)
PB8: JP1.1(COMMON) R123.2 U6.123(PB8-BOOT0)
PB9: R127.1 U6.124(PB9)
PB10: SB11.1 SB71.2 U6.62(PB10)
PB11: SB8.1 SB10.1 SB67.2 U6.65(PB11)
PB12: SB7.1 SB65.2 U6.66(PB12)
PB13: SB5.1 SB63.2 U6.67(PB13)
PB14: R35.1 U6.68(PB14)
PB15: R36.1 U6.69(PB15)
PC0: SB29.2 SB99.2 U6.22(PC0)
PC1: R130.2 SB115.2 U6.23(PC1)
PC2: R133.2 SB113.2 U6.24(PC2)
PC3: R131.2 SB114.2 U6.25(PC3)
PC4: R116.2 SB100.2 U6.37(PC4)
PC5: SB20.2 U6.38(PC5)
PC6: SB9.2 SB49.2 U6.80(PC6)
PC7: SB6.2 SB50.2 U6.81(PC7)
PC8: R26.2 SB51.2 U6.87(PC8)
PC9: R49.2 U6.88(PC9)
PC10: SB12.2 SB64.2 U6.100(PC10)
PC11: SB13.2 SB68.2 U6.101(PC11)
PC12: SB15.2 SB66.2 U6.102(PC12)
PC13: R141.2 U6.7(PC13)
PC14: U6.8(PC14_-_OSC32_IN) ; port PC14-OSC32_IN
PC15: U6.9(PC15_-_OSC32_OUT) ; port PC15-OSC32_OUT
PD0: R83.1 U6.108(PD0)
PD1: R85.1 U6.109(PD1)
PD2: SB17.2 SB123.1 U6.112(PD2)
PD3: R90.1 U6.113(PD3)
PD4: R94.1 SB89.2 U6.114(PD4)
PD5: R97.1 U6.115(PD5)
PD6: R98.1 U6.116(PD6)
PD7: R101.1 SB92.2 U6.117(PD7)
PD8: R34.1 SB55.2 U6.70(PD8)
PD9: R37.1 SB56.2 U6.71(PD9)
PD10: R38.1 SB60.2 U6.72(PD10)
PD11: R39.1 SB58.2 U6.73(PD11)
PD12: R42.1 SB59.2 U6.74(PD12)
PD13: R41.1 SB57.2 U6.75(PD13)
PD14: R29.1 SB70.2 U6.76(PD14)
PD15: R40.1 SB61.2 U6.77(PD15)
PD_CC1: SB21.2 ; port TYPEC.PD_CC1  [project net CON1_CC1]
PD_CC2: SB96.2 ; port TYPEC.PD_CC2  [project net CON1_CC2]
PD_DBCC1: SB54.1 ; port TYPEC.PD_DBCC1
PD_DBCC2: SB53.1 ; port TYPEC.PD_DBCC2
PE0: R148.2 U6.125(PE0)
PE1: R149.2 U6.126(PE1)
PE2: R147.2 SB103.2 SB111.2 U6.1(PE2)
PE3: R145.2 R146.2 SB110.2 SB118.2 U6.2(PE3)
PE4: R143.2 R144.2 SB107.2 SB109.2 U6.3(PE4)
PE5: SB28.2 SB97.2 U6.4(PE5)
PE6: R142.2 U6.5(PE6)
PE7: R84.2 SB83.2 U6.53(PE7)
PE8: R82.2 SB79.2 U6.54(PE8)
PE9: R79.2 SB78.2 U6.55(PE9)
PE10: R75.2 SB77.2 U6.56(PE10)
PE11: R71.2 SB76.2 U6.57(PE11)
PE12: R69.2 SB74.2 U6.58(PE12)
PE13: R63.2 SB73.2 U6.59(PE13)
PE14: R62.2 SB72.2 U6.60(PE14)
PE15: R60.2 SB69.2 U6.61(PE15)
PF0: U6.19(PF0_-_OSC_IN) ; port PF0-OSC_IN
PF1: U6.20(PF1_-_OSC_OUT) ; port PF1-OSC_OUT
PF2: R132.1 U6.26(PF2)
PF3: R139.1 U6.10(PF3)
PF4: R140.1 U6.11(PF4)
PF5: R137.1 U6.14(PF5)
PF6: R43.1 SB52.2 U6.97(PF6)
PF7: R138.1 SB108.2 U6.15(PF7)
PF8: R135.1 SB106.2 U6.16(PF8)
PF9: R134.1 U6.17(PF9)
PF10: R136.1 SB112.2 U6.18(PF10)
PF11: R96.1 U6.48(PF11)
PF12: R93.1 U6.49(PF12)
PF13: R89.1 U6.50(PF13)
PF14: R88.1 U6.51(PF14)
PF15: R87.1 U6.52(PF15)
PG0: R48.1 U6.82(PG0)
PG1: R28.1 U6.83(PG1)
PG2: R50.1 U6.84(PG2)
PG3: R27.1 U6.85(PG3)
PG4: R53.1 U6.86(PG4)
PG5: R68.1 U6.103(PG5)
PG6: R70.1 U6.104(PG6)
PG7: R74.1 U6.105(PG7)
PG8: R78.1 U6.106(PG8)
PG9: R81.1 U6.107(PG9)
QSPI_BK1_IO0: R102.2 ; port QSPI.QSPI_BK1_IO0
QSPI_BK1_IO1: R108.2 ; port QSPI.QSPI_BK1_IO1
QSPI_BK1_IO2: R118.1 ; port QSPI.QSPI_BK1_IO2
QSPI_BK1_IO3: R121.1 ; port QSPI.QSPI_BK1_IO3
QSPI_BK1_NCS: R150.1 ; port QSPI.QSPI_BK1_NCS
QSPI_BK2_IO0: R130.1 ; port QSPI.QSPI_BK2_IO0
QSPI_BK2_IO1: R133.1 ; port QSPI.QSPI_BK2_IO1
QSPI_BK2_IO2: R131.1 ; port QSPI.QSPI_BK2_IO2
QSPI_BK2_IO3: R116.1 ; port QSPI.QSPI_BK2_IO3
QSPI_BK2_NCS: R90.2 ; port QSPI.QSPI_BK2_NCS
QSPI_CLK: R129.1 ; port QSPI.QSPI_CLK
RS485_DIR: SB123.2 ; port RS485_DIR
SAI_FS_A: SB107.1 ; port Audio.SAI_FSA
SAI_MCLK_A: SB111.1 ; port Audio.SAI_MCKA
SAI_SCK_A: R30.1 ; port Audio.SAI_SCKA
SAI_SD_A: R98.2 ; port Audio.SAI_SDA
SAI_SD_B: SB110.1 ; port Audio.SAI_SDB
SmartCard_CLK: SB15.1 ; port SmartCard_CLK
SmartCard_IO: SB12.1 ; port SmartCard_IO
SOURCE_EN: SB13.1 ; port TYPEC.SOURCE_EN
SPI2_MISO: R35.2 ; port SPI.SPI2_MISO
SPI2_MOSI: R36.2 ; port SPI.SPI2_MOSI
SPI2_SCK: R134.2 ; port SPI.SPI2_SCK
TAMPER_KEY: R141.1 ; port TAMPER_KEY
TRACECLK: R147.1 ; port TRACE.TRACECLK
TRACED0: R145.1 ; port TRACE.TRACED0
TRACED1: R144.1 ; port TRACE.TRACED1
TRACED2: SB28.1 ; port TRACE.TRACED2
TRACED3: R142.1 ; port TRACE.TRACED3
USART1_RX: SB3.1 ; port USART1_RX
USART1_TX: SB4.1 ; port USART1_TX
USB_DM: R46.1 ; port USB-FS.USB_DM
USB_DP: R45.1 ; port USB-FS.USB_DP
uSD_CS: R135.2 ; port SPI.uSD_CS
VSENSE: SB29.1 ; port TYPEC.VSENSE
NetC49_2: SB10.2 ; port BK_Sense
NetC171_2: SB116.2 ; port ADC_OUTP

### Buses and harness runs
bus FMC_A[0..18]
bus FMC_D[0..15]
bus PA[0..15] = port PA[0..15]
bus PB[0..15] = port PB[0..15]
bus PC[0..15] = port PC[0..15]
bus PD[0..15] = port PD[0..15]
bus PE[0..15] = port PE[0..15]
bus PF[0..15] = port PF[0..15]
bus PG[0..15] = port PG[0..15]

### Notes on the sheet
- STM32G474QET6 MCU I/Os
- QSPI
- LCD and MircoSD
- Audio
- TIM1_BKIN
  TIM1_CH1
  TIM1_CH1N
  TIM1_CH2
  TIM1_CH2N
  TIM1_CH3
  TIM1_CH3N
  TIM2_CH1
  TIM2_CH2
  TIM2_CH3
  TIM2_ETR
  TIM3_CH1
  TIM3_CH2
  TIM3_ETR
  GPIO1
  GPIO2
  ADC2_IN5
  ADC12_IN7
  ADC4_IN12/5_IN12
  ADC4_IN13/5_IN13
  TIM8_BKIN
  TIM8_CH1
  TIM8_CH1N
  TIM8_CH2
  TIM8_CH2N
  TIM8_CH3
  TIM8_CH3N
  TIM5_CH1
  TIM5_CH2
  TIM5_CH3
  TIM5_ETR
  GPIO3
  GPIO4
  ADC3_IN4
  ADC4_IN1
  DAC1_OUT1
  DAC1_OUT2
  ADC12_IN8
  ADC12_IN9
  ADC12_IN6
  ADC345_IN7
  ADC345_IN9
  ADC345_IN10
  OPAMP1_VINP
  OPAMP1_VINM
  OPAMP1_VOUT
  OPAMP2_VINP
  OPAMP2_VINP
  OPAMP2_VINM
  OPAMP2_VOUT
  OPAMP4_VINP
  OPAMP4_VINP
  OPAMP4_VINM
  OPAMP4_VOUT
  OPAMP3_VINP
  OPAMP3_VINM
  OPAMP3_VOUT
- (near JP1) Open
- (near JP1) CAN1_RX
- USB-FS

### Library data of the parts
JP1 = MCD-00045: as JP10 on sheet Top
R26 R30 R35 R36 R43-R47 R49 R54 R70 R74 R78 R81 R94 R96-R98 R101 R107 R109 R112 R123 R127 R134 R135 R141 R142 R144 R145 R147-R149 = MCD-00052: Resistor,0R,0402,5%,1/16W; Manufacturer_Part_Number: RC0402JR-070RL; Manufacturer: YAGEO; Provided_By: SUBCO; Initial_Board_Reference: MB1274; Path: ws/MCD_ApplicationBoards/Lists/MCDPARTSdatabase; Item Type: Item
R27-R29 R34 R37-R42 R48 R50 R53 R60 R62 R63 R68 R69 R71 R75 R79 R82-R85 R87-R90 R93 R102 R108 R116 R118 R121 R130-R133 R136-R140 R143 R146 R150 = MCD-00052: Resistor,0R,0402,5%,1/16W
R73 R80 = MCD-00217: Resistor,1K5,0603,1%,1/10W; Manufacturer_Part_Number: RC0603FR-071K5L; Manufacturer: YAGEO; BMS_Part_Number: 9129766; Provided_By: SUBCO; Initial_Board_Reference: MB1319; Path: ws/MCD_ApplicationBoards/Lists/MCDPARTSdatabase; Item Type: Item
R129 = MCD-00455: Resistor,33R,0402,1%,1/16W; Manufacturer_Part_Number: RC0402FR-0733RL; Manufacturer: YAGEO; Provided_By: SUBCO; Initial_Board_Reference: MBxxxx; Path: ws/MCD_ApplicationBoards/Lists/MCDPARTSdatabase; Item Type: Item
SB3-SB9 SB11-SB13 SB15 SB18 SB20 SB21 SB23-SB29 SB96 SB107 SB110 SB111 SB123 = MCD-00071: Solder Bridge ON; Part_Type: Mechanical; Manufacturer_Part_Number: RC0603JR-070RL; Manufacturer: YAGEO; Provided_By: SUBCO; Initial_Board_Reference: MB1274; Path: ws/MCD_ApplicationBoards/Lists/MCDPARTSdatabase; Item Type: Item
SB10 SB17 SB49-SB74 SB76-SB80 SB83 SB89 SB91-SB95 SB97-SB101 SB103-SB106 SB108 SB109 SB112-SB118 = MCD-00072: Solder Bridge OFF; Part_Type: Mechanical; Manufacturer_Part_Number: RC0603JR-070RL; Manufacturer: YAGEO; Provided_By: SUBCO; Initial_Board_Reference: MB1274; Path: ws/MCD_ApplicationBoards/Lists/MCDPARTSdatabase; Item Type: Item
U6 = MCD-01212: MCU, ARM Cortex-M4 32-bit, 512KB Flash, 128KB RAM, With Crypto; Part_Type: IC; Manufacturer: STMICROELECTRONICS; BMS_Part_Number: 9175327; Part_Preference: Recommended; Manufacturer_HQ_COO: EU; Order_Code_RS: 193-9856; Component_Country_Of_Origin: Taiwan; ShowFields: YES; ID: 3284

## Sheet FMC_Memory.SchDoc: FMC Memeory
size A4; Date: Not used; ApprovedBy: Not used; CheckedBy: Not used; Author: Not used; CompanyName: STMicroelectronics; DrawnBy: Not used; Engineer: Not used; Organization: Not used; Address1: Not used; Address2: Not used; Address3: Not used; Address4: Not used; DocumentNumber: Not used; Revision: Not used; SheetNumber: 7; SheetTotal: 22
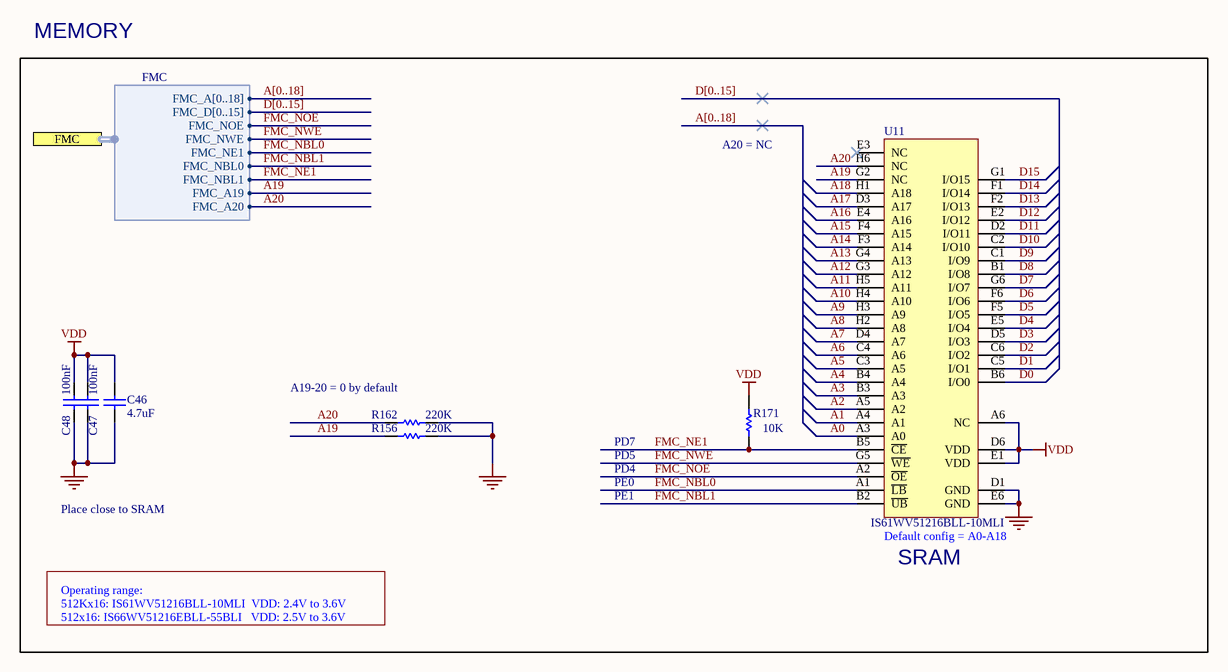
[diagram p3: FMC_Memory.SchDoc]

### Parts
C46  value 4.7uF  [C0603]  (hidden comment: Capacitor)
C47  value 100nF  [C0402]  (hidden comment: Capacitor)
C48  value 100nF  [C0402]  (hidden comment: Capacitor)
R156  value 220K  [R0402]  (hidden comment: Resistor)
R162  value 220K  [R0402]  (hidden comment: Resistor)
R171  value 10K  [R0402]  (hidden comment: Resistor)
U11  IS61WV51216BLL-10MLI  [ICC_MINI-BGA48_9X11_P075]

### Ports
FMC (harness FMC)

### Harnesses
FMC: FMC_NWE, FMC_NOE, FMC_NE1, FMC_A[0..18], FMC_D[0..15], FMC_NBL0, FMC_NBL1, FMC_A19, FMC_A20

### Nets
GND: C46.1 C47.2 C48.2 R156.1 R162.1 U11.D1(GND) U11.E6(GND)
VDD: C46.2 C47.1 C48.1 R171.2 U11.A6(NC) U11.D6(VDD) U11.E1(VDD)
A0: U11.A3(A0)
A1: U11.A4(A1)
A2: U11.A5(A2)
A3: U11.B3(A3)
A4: U11.B4(A4)
A5: U11.C3(A5)
A6: U11.C4(A6)
A7: U11.D4(A7)
A8: U11.H2(A8)
A9: U11.H3(A9)
A10: U11.H4(A10)
A11: U11.H5(A11)
A12: U11.G3(A12)
A13: U11.G4(A13)
A14: U11.F3(A14)
A15: U11.F4(A15)
A16: U11.E4(A16)
A17: U11.D3(A17)
A18: U11.H1(A18)
A19: R156.2 U11.G2(NC) ; port FMC.FMC_A19
A20: R162.2 U11.H6(NC) ; port FMC.FMC_A20
D0: U11.B6(I/O0)
D1: U11.C5(I/O1)
D2: U11.C6(I/O2)
D3: U11.D5(I/O3)
D4: U11.E5(I/O4)
D5: U11.F5(I/O5)
D6: U11.F6(I/O6)
D7: U11.G6(I/O7)
D8: U11.B1(I/O8)
D9: U11.C1(I/O9)
D10: U11.C2(I/O10)
D11: U11.D2(I/O11)
D12: U11.E2(I/O12)
D13: U11.F2(I/O13)
D14: U11.F1(I/O14)
D15: U11.G1(I/O15)
FMC_NBL0: U11.A1(~{LB}) ; port FMC.FMC_NE1
FMC_NBL1: U11.B2(~{UB}) ; port FMC.FMC_NBL0
FMC_NE1: R171.1 U11.B5(~{CE}) ; port FMC.FMC_NBL1
FMC_NOE: U11.A2(~{OE}) ; port FMC.FMC_NOE
FMC_NWE: U11.G5(~{WE}) ; port FMC.FMC_NWE

Not connected (* = marked no-connect by the designer): U11 E3(NC)*

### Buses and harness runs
bus A[0..18]
bus D[0..15]

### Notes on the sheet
- MEMORY
- A20 = NC
- A19-20 = 0 by default
- PD5
- PD7
- Place close to SRAM
- PE1
- PE0
- PD4
- Operating range:
- (near U11) Default config = A0-A18
- (near U11) SRAM
- 512Kx16: IS61WV51216BLL-10MLI  VDD: 2.4V to 3.6V
- 512x16: IS66WV51216EBLL-55BLI   VDD: 2.5V to 3.6V

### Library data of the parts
C46 = MCD-00009: Capacitor, MLCC, 4.7uF, 16V, X5R, 10%, 0603, T=0.8mm; Manufacturer_Part_Number: CC0603KRX5R7BB475; Manufacturer: YAGEO; Provided_By: SUBCO; Initial_Board_Reference: MB1274; Path: ws/MCD_ApplicationBoards/Lists/MCDPARTSdatabase; Item Type: Item
C47 C48 = MCD-00006: Capacitor, MLCC, 100nF, 16V, X7R, 10%, 0402, T=0.5mm; Manufacturer_Part_Number: CC0402KRX7R7BB104; Manufacturer: YAGEO; Alternate_Manufacturer_Part_Number: GCM155R71C104KA55D; Alternate_Manufacturer: MURATA; Provided_By: SUBCO; Initial_Board_Reference: MB1274; Path: ws/MCD_ApplicationBoards/Lists/MCDPARTSdatabase; Item Type: Item
R156 R162 = MCD-00164: Resistor,220K,0402,1%,1/16W; Manufacturer_Part_Number: RC0402FR-07220KL; Manufacturer: YAGEO; Provided_By: SUBCO; Initial_Board_Reference: MB1264; Path: ws/MCD_ApplicationBoards/Lists/MCDPARTSdatabase; Item Type: Item
R171 = MCD-00053: Resistor,10K,0402,1%,1/16W; Manufacturer_Part_Number: RC0402FR-0710KL; Manufacturer: YAGEO; Provided_By: SUBCO; Initial_Board_Reference: MB1274; Path: ws/MCD_ApplicationBoards/Lists/MCDPARTSdatabase; Item Type: Item
U11 = MCD-01071: SRAM, 8Mb, 10ns, 512Kx16bits, Async, 3.3v; Manufacturer: ISSI; Part_Type: IC; Provided_By: SUBCO; Initial_Board_Reference: MB1361; Path: ws/MCD_ApplicationBoards/Lists/MCDPARTSdatabase; Item Type: Item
